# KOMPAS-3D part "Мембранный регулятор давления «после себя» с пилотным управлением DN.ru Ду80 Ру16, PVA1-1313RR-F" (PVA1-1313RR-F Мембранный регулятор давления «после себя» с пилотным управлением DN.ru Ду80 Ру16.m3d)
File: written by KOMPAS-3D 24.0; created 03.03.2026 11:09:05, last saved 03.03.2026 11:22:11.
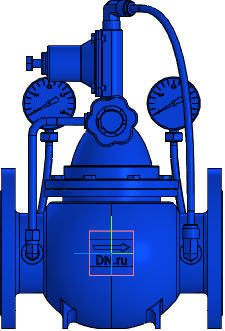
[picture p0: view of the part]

Document properties: Автор: R2D2; Полное имя файла: PVA1-1313RR-F Мембранный регулятор давления «после себя» с пилотным управлением DN.ru Ду80 Ру16.cdw

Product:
- Part/product: Мембранный регулятор давления «после себя» с пилотным управлением DN.ru Ду80 Ру16  | designation PVA1-1313RR-F
    Масса: 13
    Раздел спецификации: Прочие изделия
    Форматы листов документа: A3
    Примечание: D230-10619
    additional columns: D230-10619

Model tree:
1. Операция без истории:1

Expressions: PVA1-1313RR-F
Referenced files in C:\Program Files\ASCON\KOMPAS-3D v24\Libs\Pipeline\: StylesTemplate.a3d, TemplateHPH, InsulationStylesTemplate.a3d, Insulation
Referenced files in C:\Program Files\ASCON\KOMPAS-3D v24\Templates\: Констр. чертеж А3 гориз. перв. лист.cdt
Referenced files in E:\Работа\Зайцев\PVA1-1313RR-F Мембранный регулятор давления «после себя» с пилотным управлением DN.ru Ду50-200 Ру16\DN80\исходные материалы\: 
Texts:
  Отводы ГОСТ 17375-2001
  Констр. чертеж А3 гориз. перв. лист.cdt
